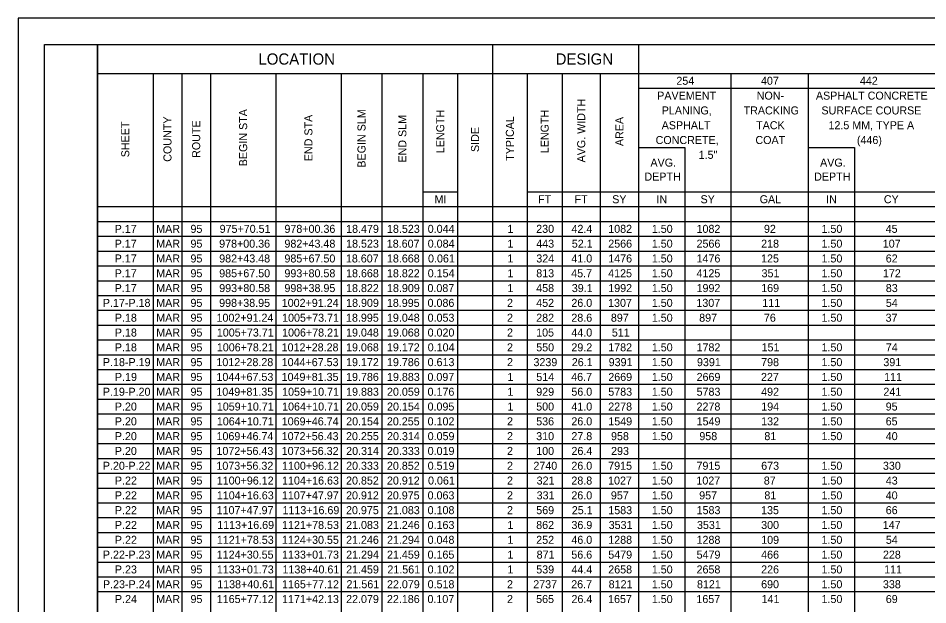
# Model space of a CAD drawing. Extents: x 0 to 34, y 0 to 22.
# Drawn here: x 0 to 17.22, y 10.91 to 22 of the extents above; entities that cross this region are included whole.
import ezdxf

# ---------------------------------------------------------------- set-up
doc = ezdxf.new("R2010")
doc.units = 0
for name, color, linetype in [('SH_Border', 7, 'Continuous'), ('SH_Cut_Line', 7, 'Continuous'), ('SH_Text', 7, 'Continuous')]:
    doc.layers.add(name, color=color, linetype=linetype)

msp = doc.modelspace()

# ---------------------------------------------------------------- linework, layer by layer
at = {"layer": 'SH_Border'}
for points in [[(0.5, 21.5), (1.5, 21.5), (1.5, 0.5), (0.5, 0.5)], [(1.5, 21.5), (33.5, 21.5), (33.5, 0.5), (1.5, 0.5)]]:
    msp.add_lwpolyline(points, close=True, dxfattribs=at)
at = {"layer": 'SH_Cut_Line'}
msp.add_lwpolyline([(0, 0), (34, 0), (34, 22), (0, 22)], close=True, dxfattribs=at)
at = {"layer": 'SH_Text'}
for p, q in [((1.5, 21.5), (32.011, 21.5)), ((1.5, 21.5), (1.5, 0.512)), ((8.979, 21.5), (8.979, 0.792)), ((11.747, 21.5), (11.747, 0.512)), ((1.5, 20.956), (32.011, 20.956)), ((2.554, 20.956), (2.554, 7.233)), ((3.098, 20.956), (3.098, 7.233)), ((3.642, 20.956), (3.642, 7.233)), ((4.877, 20.956), (4.877, 7.233)), ((6.113, 20.956), (6.113, 7.233)), ((6.887, 20.956), (6.887, 7.233)), ((7.661, 20.956), (7.661, 7.233)), ((8.32, 20.956), (8.32, 7.233)), ((9.638, 20.956), (9.638, 3.592)), ((10.297, 20.956), (10.297, 0.792)), ((11.022, 20.956), (11.022, 0.792)), ((13.493, 20.956), (13.493, 0.512)), ((14.96, 20.956), (14.96, 0.512)), ((11.747, 20.676), (27.48, 20.676)), ((11.747, 19.556), (12.62, 19.556)), ((12.62, 19.556), (12.62, 0.512)), ((14.96, 19.556), (15.833, 19.556)), ((15.833, 19.556), (15.833, 0.512)), ((7.661, 18.716), (8.32, 18.716)), ((9.638, 18.716), (27.48, 18.716)), ((1.5, 18.436), (32.011, 18.436)), ((1.5, 18.156), (32.011, 18.156)), ((1.5, 17.876), (32.011, 17.876)), ((1.5, 17.596), (32.011, 17.596)), ((1.5, 17.315), (32.011, 17.315)), ((1.5, 17.035), (32.011, 17.035)), ((1.5, 16.755), (32.011, 16.755)), ((1.5, 16.475), (32.011, 16.475)), ((1.5, 16.195), (32.011, 16.195)), ((1.5, 15.915), (32.011, 15.915)), ((1.5, 15.635), (32.011, 15.635)), ((1.5, 15.355), (32.011, 15.355)), ((1.5, 15.075), (32.011, 15.075)), ((1.5, 14.795), (32.011, 14.795)), ((1.5, 14.515), (32.011, 14.515)), ((1.5, 14.235), (32.011, 14.235)), ((1.5, 13.955), (32.011, 13.955)), ((1.5, 13.675), (32.011, 13.675)), ((1.5, 13.395), (32.011, 13.395)), ((1.5, 13.114), (32.011, 13.114)), ((1.5, 12.834), (32.011, 12.834)), ((1.5, 12.554), (32.011, 12.554)), ((1.5, 12.274), (32.011, 12.274)), ((1.5, 11.994), (32.011, 11.994)), ((1.5, 11.714), (32.011, 11.714)), ((1.5, 11.434), (32.011, 11.434)), ((1.5, 11.154), (32.011, 11.154))]:
    msp.add_line(p, q, dxfattribs=at)

# ---------------------------------------------------------------- texts
for s, height, p in [('LOCATION', 0.2122, (4.548, 21.122)), ('DESIGN', 0.2122, (10.176, 21.122)), ('254', 0.1516, (12.462, 20.741)), ('407', 0.1516, (14.064, 20.741)), ('442', 0.1516, (15.937, 20.741)), ('PAVEMENT', 0.1516, (12.099, 20.46)), ('NON-', 0.1516, (13.983, 20.46)), ('ASPHALT CONCRETE', 0.15157, (15.104, 20.46)), ('PLANING,', 0.1516, (12.185, 20.18)), ('TRACKING', 0.1516, (13.735, 20.18)), ('SURFACE COURSE', 0.15157, (15.209, 20.18)), ('ASPHALT', 0.1516, (12.184, 19.9)), ('TACK', 0.1516, (13.972, 19.9)), ('12.5 MM, TYPE A', 0.15157, (15.342, 19.9)), ('CONCRETE,', 0.1516, (12.069, 19.62)), ('COAT', 0.1516, (13.959, 19.62)), ('(446)', 0.1516, (15.88, 19.62)), ('1.5"', 0.1516, (12.884, 19.34)), ('AVG. ', 0.1516, (11.971, 19.193)), ('AVG. ', 0.1516, (15.183, 19.193)), ('DEPTH', 0.1516, (11.857, 18.928)), ('DEPTH', 0.1516, (15.07, 18.928)), ('MI', 0.1516, (7.883, 18.5)), ('FT', 0.1516, (9.842, 18.5)), ('FT', 0.1516, (10.534, 18.5)), ('SY', 0.1516, (11.247, 18.5)), ('IN', 0.1516, (12.085, 18.5)), ('SY', 0.1516, (12.92, 18.5)), ('GAL', 0.1516, (14.039, 18.5)), ('IN', 0.1516, (15.298, 18.5)), ('CY', 0.1516, (16.39, 18.5)), ('P.17', 0.1516, (1.827, 17.94)), ('MAR', 0.1516, (2.614, 17.94)), ('95', 0.1516, (3.262, 17.94)), ('975+70.51', 0.1516, (3.814, 17.94)), ('978+00.36', 0.1516, (5.041, 17.94)), ('18.479', 0.1516, (6.209, 17.94)), ('18.523', 0.1516, (6.983, 17.94)), ('0.044', 0.1516, (7.754, 17.94)), ('1', 0.152, (9.263, 17.94)), ('230', 0.1516, (9.808, 17.94)), ('42.4', 0.1516, (10.476, 17.94)), ('1082', 0.1516, (11.172, 17.94)), ('1.50', 0.1516, (11.997, 17.94)), ('1082', 0.1516, (12.844, 17.94)), ('92', 0.1516, (14.12, 17.94)), ('1.50', 0.1516, (15.21, 17.94)), ('45', 0.1516, (16.425, 17.94)), ('P.17', 0.1516, (1.827, 17.66)), ('MAR', 0.1516, (2.614, 17.66)), ('95', 0.1516, (3.262, 17.66)), ('978+00.36', 0.1516, (3.805, 17.66)), ('982+43.48', 0.1516, (5.041, 17.66)), ('18.523', 0.1516, (6.209, 17.66)), ('18.607', 0.1516, (6.979, 17.66)), ('0.084', 0.1516, (7.754, 17.66)), ('1', 0.152, (9.263, 17.66)), ('443', 0.1516, (9.809, 17.66)), ('52.1', 0.1516, (10.482, 17.66)), ('2566', 0.1516, (11.172, 17.66)), ('1.50', 0.1516, (11.997, 17.66)), ('2566', 0.1516, (12.844, 17.66)), ('218', 0.1516, (14.067, 17.66)), ('1.50', 0.1516, (15.21, 17.66)), ('107', 0.1516, (16.37, 17.66)), ('P.17', 0.1516, (1.827, 17.38)), ('MAR', 0.1516, (2.614, 17.38)), ('95', 0.1516, (3.262, 17.38)), ('982+43.48', 0.1516, (3.806, 17.38)), ('985+67.50', 0.1516, (5.041, 17.38)), ('18.607', 0.1516, (6.205, 17.38)), ('18.668', 0.1516, (6.982, 17.38)), ('0.061', 0.1516, (7.76, 17.38)), ('1', 0.152, (9.263, 17.38)), ('324', 0.1516, (9.81, 17.38)), ('41.0', 0.1516, (10.474, 17.38)), ('1476', 0.1516, (11.172, 17.38)), ('1.50', 0.1516, (11.997, 17.38)), ('1476', 0.1516, (12.844, 17.38)), ('125', 0.1516, (14.066, 17.38)), ('1.50', 0.1516, (15.21, 17.38)), ('62', 0.1516, (16.426, 17.38)), ('P.17', 0.1516, (1.827, 17.1)), ('MAR', 0.1516, (2.614, 17.1)), ('95', 0.1516, (3.262, 17.1)), ('985+67.50', 0.1516, (3.806, 17.1)), ('993+80.58', 0.1516, (5.041, 17.1)), ('18.668', 0.1516, (6.208, 17.1)), ('18.822', 0.1516, (6.982, 17.1)), ('0.154', 0.1516, (7.754, 17.1)), ('1', 0.152, (9.263, 17.1)), ('813', 0.1516, (9.809, 17.1)), ('45.7', 0.1516, (10.471, 17.1)), ('4125', 0.1516, (11.171, 17.1)), ('1.50', 0.1516, (11.997, 17.1)), ('4125', 0.1516, (12.843, 17.1)), ('351', 0.1516, (14.075, 17.1)), ('1.50', 0.1516, (15.21, 17.1)), ('172', 0.1516, (16.373, 17.1)), ('P.17', 0.1516, (1.827, 16.82)), ('MAR', 0.1516, (2.614, 16.82)), ('95', 0.1516, (3.262, 16.82)), ('993+80.58', 0.1516, (3.806, 16.82)), ('998+38.95', 0.1516, (5.041, 16.82)), ('18.822', 0.1516, (6.208, 16.82)), ('18.909', 0.1516, (6.983, 16.82)), ('0.087', 0.1516, (7.749, 16.82)), ('1', 0.152, (9.263, 16.82)), ('458', 0.1516, (9.808, 16.82)), ('39.1', 0.1516, (10.482, 16.82)), ('1992', 0.1516, (11.172, 16.82)), ('1.50', 0.1516, (11.997, 16.82)), ('1992', 0.1516, (12.844, 16.82)), ('169', 0.1516, (14.068, 16.82)), ('1.50', 0.1516, (15.21, 16.82)), ('83', 0.1516, (16.427, 16.82)), ('P.17-P.18', 0.1516, (1.603, 16.54)), ('MAR', 0.1516, (2.614, 16.54)), ('95', 0.1516, (3.262, 16.54)), ('998+38.95', 0.1516, (3.805, 16.54)), ('1002+91.24', 0.1516, (4.99, 16.54)), ('18.909', 0.1516, (6.209, 16.54)), ('18.995', 0.1516, (6.981, 16.54)), ('0.086', 0.1516, (7.751, 16.54)), ('2', 0.152, (9.255, 16.54)), ('452', 0.1516, (9.808, 16.54)), ('26.0', 0.1516, (10.474, 16.54)), ('1307', 0.1516, (11.169, 16.54)), ('1.50', 0.1516, (11.997, 16.54)), ('1307', 0.1516, (12.841, 16.54)), ('111', 0.1516, (14.089, 16.54)), ('1.50', 0.1516, (15.21, 16.54)), ('54', 0.1516, (16.428, 16.54)), ('P.18', 0.1516, (1.83, 16.259)), ('MAR', 0.1516, (2.614, 16.259)), ('95', 0.1516, (3.262, 16.259)), ('1002+91.24', 0.1516, (3.755, 16.259)), ('1005+73.71', 0.1516, (4.997, 16.259)), ('18.995', 0.1516, (6.207, 16.259)), ('19.048', 0.1516, (6.982, 16.259)), ('0.053', 0.1516, (7.752, 16.259)), ('2', 0.152, (9.255, 16.259)), ('282', 0.1516, (9.808, 16.259)), ('28.6', 0.1516, (10.473, 16.259)), ('897', 0.1516, (11.222, 16.259)), ('1.50', 0.1516, (11.997, 16.259)), ('897', 0.1516, (12.894, 16.259)), ('76', 0.1516, (14.119, 16.259)), ('1.50', 0.1516, (15.21, 16.259)), ('37', 0.1516, (16.423, 16.259)), ('P.18', 0.1516, (1.83, 15.979)), ('MAR', 0.1516, (2.614, 15.979)), ('95', 0.1516, (3.262, 15.979)), ('1005+73.71', 0.1516, (3.761, 15.979)), ('1006+78.21', 0.1516, (4.997, 15.979)), ('19.048', 0.1516, (6.208, 15.979)), ('19.068', 0.1516, (6.982, 15.979)), ('0.020', 0.1516, (7.752, 15.979)), ('2', 0.152, (9.255, 15.979)), ('105', 0.1516, (9.807, 15.979)), ('44.0', 0.1516, (10.474, 15.979)), ('511', 0.1516, (11.24, 15.979)), ('P.18', 0.1516, (1.83, 15.699)), ('MAR', 0.1516, (2.614, 15.699)), ('95', 0.1516, (3.262, 15.699)), ('1006+78.21', 0.1516, (3.761, 15.699)), ('1012+28.28', 0.1516, (4.988, 15.699)), ('19.068', 0.1516, (6.208, 15.699)), ('19.172', 0.1516, (6.982, 15.699)), ('0.104', 0.1516, (7.754, 15.699)), ('2', 0.152, (9.255, 15.699)), ('550', 0.1516, (9.808, 15.699)), ('29.2', 0.1516, (10.474, 15.699)), ('1782', 0.1516, (11.172, 15.699)), ('1.50', 0.1516, (11.997, 15.699)), ('1782', 0.1516, (12.844, 15.699)), ('151', 0.1516, (14.075, 15.699)), ('1.50', 0.1516, (15.21, 15.699)), ('74', 0.1516, (16.428, 15.699)), ('P.18-P.19', 0.1516, (1.604, 15.419)), ('MAR', 0.1516, (2.614, 15.419)), ('95', 0.1516, (3.262, 15.419)), ('1012+28.28', 0.1516, (3.753, 15.419)), ('1044+67.53', 0.1516, (4.989, 15.419)), ('19.172', 0.1516, (6.208, 15.419)), ('19.786', 0.1516, (6.982, 15.419)), ('0.613', 0.1516, (7.752, 15.419)), ('2', 0.152, (9.255, 15.419)), ('3239', 0.1516, (9.756, 15.419)), ('26.1', 0.1516, (10.482, 15.419)), ('9391', 0.1516, (11.18, 15.419)), ('1.50', 0.1516, (11.997, 15.419)), ('9391', 0.1516, (12.852, 15.419)), ('798', 0.1516, (14.067, 15.419)), ('1.50', 0.1516, (15.21, 15.419)), ('391', 0.1516, (16.381, 15.419)), ('P.19', 0.1516, (1.832, 15.139)), ('MAR', 0.1516, (2.614, 15.139)), ('95', 0.1516, (3.262, 15.139)), ('1044+67.53', 0.1516, (3.754, 15.139)), ('1049+81.35', 0.1516, (4.988, 15.139)), ('19.786', 0.1516, (6.208, 15.139)), ('19.883', 0.1516, (6.983, 15.139)), ('0.097', 0.1516, (7.749, 15.139)), ('1', 0.152, (9.263, 15.139)), ('514', 0.1516, (9.81, 15.139)), ('46.7', 0.1516, (10.471, 15.139)), ('2669', 0.1516, (11.173, 15.139)), ('1.50', 0.1516, (11.997, 15.139)), ('2669', 0.1516, (12.845, 15.139)), ('227', 0.1516, (14.064, 15.139)), ('1.50', 0.1516, (15.21, 15.139)), ('111', 0.1516, (16.396, 15.139)), ('P.19-P.20', 0.1516, (1.603, 14.859)), ('MAR', 0.1516, (2.614, 14.859)), ('95', 0.1516, (3.262, 14.859)), ('1049+81.35', 0.1516, (3.752, 14.859)), ('1059+10.71', 0.1516, (4.997, 14.859)), ('19.883', 0.1516, (6.209, 14.859)), ('20.059', 0.1516, (6.983, 14.859)), ('0.176', 0.1516, (7.751, 14.859)), ('1', 0.152, (9.263, 14.859)), ('929', 0.1516, (9.809, 14.859)), ('56.0', 0.1516, (10.474, 14.859)), ('5783', 0.1516, (11.173, 14.859)), ('1.50', 0.1516, (11.997, 14.859)), ('5783', 0.1516, (12.845, 14.859)), ('492', 0.1516, (14.067, 14.859)), ('1.50', 0.1516, (15.21, 14.859)), ('241', 0.1516, (16.381, 14.859)), ('P.20', 0.1516, (1.83, 14.579)), ('MAR', 0.1516, (2.614, 14.579)), ('95', 0.1516, (3.262, 14.579)), ('1059+10.71', 0.1516, (3.761, 14.579)), ('1064+10.71', 0.1516, (4.997, 14.579)), ('20.059', 0.1516, (6.209, 14.579)), ('20.154', 0.1516, (6.984, 14.579)), ('0.095', 0.1516, (7.751, 14.579)), ('1', 0.152, (9.263, 14.579)), ('500', 0.1516, (9.808, 14.579)), ('41.0', 0.1516, (10.474, 14.579)), ('2278', 0.1516, (11.172, 14.579)), ('1.50', 0.1516, (11.997, 14.579)), ('2278', 0.1516, (12.844, 14.579)), ('194', 0.1516, (14.069, 14.579)), ('1.50', 0.1516, (15.21, 14.579)), ('95', 0.1516, (16.425, 14.579)), ('P.20', 0.1516, (1.83, 14.299)), ('MAR', 0.1516, (2.614, 14.299)), ('95', 0.1516, (3.262, 14.299)), ('1064+10.71', 0.1516, (3.761, 14.299)), ('1069+46.74', 0.1516, (4.99, 14.299)), ('20.154', 0.1516, (6.21, 14.299)), ('20.255', 0.1516, (6.981, 14.299)), ('0.102', 0.1516, (7.752, 14.299)), ('2', 0.152, (9.255, 14.299)), ('536', 0.1516, (9.808, 14.299)), ('26.0', 0.1516, (10.474, 14.299)), ('1549', 0.1516, (11.173, 14.299)), ('1.50', 0.1516, (11.997, 14.299)), ('1549', 0.1516, (12.845, 14.299)), ('132', 0.1516, (14.067, 14.299)), ('1.50', 0.1516, (15.21, 14.299)), ('65', 0.1516, (16.425, 14.299)), ('P.20', 0.1516, (1.83, 14.019)), ('MAR', 0.1516, (2.614, 14.019)), ('95', 0.1516, (3.262, 14.019)), ('1069+46.74', 0.1516, (3.755, 14.019)), ('1072+56.43', 0.1516, (4.989, 14.019)), ('20.255', 0.1516, (6.207, 14.019)), ('20.314', 0.1516, (6.984, 14.019)), ('0.059', 0.1516, (7.753, 14.019)), ('2', 0.152, (9.255, 14.019)), ('310', 0.1516, (9.808, 14.019)), ('27.8', 0.1516, (10.474, 14.019)), ('958', 0.1516, (11.225, 14.019)), ('1.50', 0.1516, (11.997, 14.019)), ('958', 0.1516, (12.897, 14.019)), ('81', 0.1516, (14.128, 14.019)), ('1.50', 0.1516, (15.21, 14.019)), ('40', 0.1516, (16.426, 14.019)), ('P.20', 0.1516, (1.83, 13.739)), ('MAR', 0.1516, (2.614, 13.739)), ('95', 0.1516, (3.262, 13.739)), ('1072+56.43', 0.1516, (3.754, 13.739)), ('1073+56.32', 0.1516, (4.989, 13.739)), ('20.314', 0.1516, (6.21, 13.739)), ('20.333', 0.1516, (6.983, 13.739)), ('0.019', 0.1516, (7.753, 13.739)), ('2', 0.152, (9.255, 13.739)), ('100', 0.1516, (9.808, 13.739)), ('26.4', 0.1516, (10.476, 13.739)), ('293', 0.1516, (11.226, 13.739)), ('P.20-P.22', 0.1516, (1.603, 13.459)), ('MAR', 0.1516, (2.614, 13.459)), ('95', 0.1516, (3.262, 13.459)), ('1073+56.32', 0.1516, (3.753, 13.459)), ('1100+96.12', 0.1516, (4.996, 13.459)), ('20.333', 0.1516, (6.209, 13.459)), ('20.852', 0.1516, (6.982, 13.459)), ('0.519', 0.1516, (7.753, 13.459)), ('2', 0.152, (9.255, 13.459)), ('2740', 0.1516, (9.755, 13.459)), ('26.0', 0.1516, (10.474, 13.459)), ('7915', 0.1516, (11.171, 13.459)), ('1.50', 0.1516, (11.997, 13.459)), ('7915', 0.1516, (12.843, 13.459)), ('673', 0.1516, (14.068, 13.459)), ('1.50', 0.1516, (15.21, 13.459)), ('330', 0.1516, (16.373, 13.459)), ('P.22', 0.1516, (1.831, 13.179)), ('MAR', 0.1516, (2.614, 13.179)), ('95', 0.1516, (3.262, 13.179)), ('1100+96.12', 0.1516, (3.76, 13.179)), ('1104+16.63', 0.1516, (4.996, 13.179)), ('20.852', 0.1516, (6.208, 13.179)), ('20.912', 0.1516, (6.982, 13.179)), ('0.061', 0.1516, (7.76, 13.179)), ('2', 0.152, (9.255, 13.179)), ('321', 0.1516, (9.816, 13.179)), ('28.8', 0.1516, (10.474, 13.179)), ('1027', 0.1516, (11.169, 13.179)), ('1.50', 0.1516, (11.997, 13.179)), ('1027', 0.1516, (12.841, 13.179)), ('87', 0.1516, (14.117, 13.179)), ('1.50', 0.1516, (15.21, 13.179)), ('43', 0.1516, (16.427, 13.179)), ('P.22', 0.1516, (1.831, 12.899)), ('MAR', 0.1516, (2.614, 12.899)), ('95', 0.1516, (3.262, 12.899)), ('1104+16.63', 0.1516, (3.761, 12.899)), ('1107+47.97', 0.1516, (4.993, 12.899)), ('20.912', 0.1516, (6.208, 12.899)), ('20.975', 0.1516, (6.981, 12.899)), ('0.063', 0.1516, (7.752, 12.899)), ('2', 0.152, (9.255, 12.899)), ('331', 0.1516, (9.816, 12.899)), ('26.0', 0.1516, (10.474, 12.899)), ('957', 0.1516, (11.222, 12.899)), ('1.50', 0.1516, (11.997, 12.899)), ('957', 0.1516, (12.894, 12.899)), ('81', 0.1516, (14.128, 12.899)), ('1.50', 0.1516, (15.21, 12.899)), ('40', 0.1516, (16.426, 12.899)), ('P.22', 0.1516, (1.831, 12.619)), ('MAR', 0.1516, (2.614, 12.619)), ('95', 0.1516, (3.262, 12.619)), ('1107+47.97', 0.1516, (3.757, 12.619)), ('1113+16.69', 0.1516, (5.004, 12.619)), ('20.975', 0.1516, (6.207, 12.619)), ('21.083', 0.1516, (6.983, 12.619)), ('0.108', 0.1516, (7.752, 12.619)), ('2', 0.152, (9.255, 12.619)), ('569', 0.1516, (9.809, 12.619)), ('25.1', 0.1516, (10.482, 12.619)), ('1583', 0.1516, (11.173, 12.619)), ('1.50', 0.1516, (11.997, 12.619)), ('1583', 0.1516, (12.845, 12.619)), ('135', 0.1516, (14.066, 12.619)), ('1.50', 0.1516, (15.21, 12.619)), ('66', 0.1516, (16.426, 12.619)), ('P.22', 0.1516, (1.831, 12.339)), ('MAR', 0.1516, (2.614, 12.339)), ('95', 0.1516, (3.262, 12.339)), ('1113+16.69', 0.1516, (3.768, 12.339)), ('1121+78.53', 0.1516, (4.996, 12.339)), ('21.083', 0.1516, (6.209, 12.339)), ('21.246', 0.1516, (6.982, 12.339)), ('0.163', 0.1516, (7.752, 12.339)), ('1', 0.152, (9.263, 12.339)), ('862', 0.1516, (9.808, 12.339)), ('36.9', 0.1516, (10.475, 12.339)), ('3531', 0.1516, (11.18, 12.339)), ('1.50', 0.1516, (11.997, 12.339)), ('3531', 0.1516, (12.852, 12.339)), ('300', 0.1516, (14.067, 12.339)), ('1.50', 0.1516, (15.21, 12.339)), ('147', 0.1516, (16.37, 12.339)), ('P.22', 0.1516, (1.831, 12.058)), ('MAR', 0.1516, (2.614, 12.058)), ('95', 0.1516, (3.262, 12.058)), ('1121+78.53', 0.1516, (3.761, 12.058)), ('1124+30.55', 0.1516, (4.995, 12.058)), ('21.246', 0.1516, (6.208, 12.058)), ('21.294', 0.1516, (6.984, 12.058)), ('0.048', 0.1516, (7.752, 12.058)), ('1', 0.152, (9.263, 12.058)), ('252', 0.1516, (9.808, 12.058)), ('46.0', 0.1516, (10.474, 12.058)), ('1288', 0.1516, (11.172, 12.058)), ('1.50', 0.1516, (11.997, 12.058)), ('1288', 0.1516, (12.844, 12.058)), ('109', 0.1516, (14.068, 12.058)), ('1.50', 0.1516, (15.21, 12.058)), ('54', 0.1516, (16.428, 12.058)), ('P.22-P.23', 0.1516, (1.603, 11.778)), ('MAR', 0.1516, (2.614, 11.778)), ('95', 0.1516, (3.262, 11.778)), ('1124+30.55', 0.1516, (3.759, 11.778)), ('1133+01.73', 0.1516, (4.996, 11.778)), ('21.294', 0.1516, (6.21, 11.778)), ('21.459', 0.1516, (6.983, 11.778)), ('0.165', 0.1516, (7.751, 11.778)), ('1', 0.152, (9.263, 11.778)), ('871', 0.1516, (9.816, 11.778)), ('56.6', 0.1516, (10.473, 11.778)), ('5479', 0.1516, (11.173, 11.778)), ('1.50', 0.1516, (11.997, 11.778)), ('5479', 0.1516, (12.845, 11.778)), ('466', 0.1516, (14.067, 11.778)), ('1.50', 0.1516, (15.21, 11.778)), ('228', 0.1516, (16.373, 11.778)), ('P.23', 0.1516, (1.831, 11.498)), ('MAR', 0.1516, (2.614, 11.498)), ('95', 0.1516, (3.262, 11.498)), ('1133+01.73', 0.1516, (3.761, 11.498)), ('1138+40.61', 0.1516, (5.004, 11.498)), ('21.459', 0.1516, (6.209, 11.498)), ('21.561', 0.1516, (6.99, 11.498)), ('0.102', 0.1516, (7.752, 11.498)), ('1', 0.152, (9.263, 11.498)), ('539', 0.1516, (9.809, 11.498)), ('44.4', 0.1516, (10.476, 11.498)), ('2658', 0.1516, (11.172, 11.498)), ('1.50', 0.1516, (11.997, 11.498)), ('2658', 0.1516, (12.844, 11.498)), ('226', 0.1516, (14.067, 11.498)), ('1.50', 0.1516, (15.21, 11.498)), ('111', 0.1516, (16.396, 11.498)), ('P.23-P.24', 0.1516, (1.605, 11.218)), ('MAR', 0.1516, (2.614, 11.218)), ('95', 0.1516, (3.262, 11.218)), ('1138+40.61', 0.1516, (3.768, 11.218)), ('1165+77.12', 0.1516, (4.996, 11.218)), ('21.561', 0.1516, (6.216, 11.218)), ('22.079', 0.1516, (6.983, 11.218)), ('0.518', 0.1516, (7.752, 11.218)), ('2', 0.152, (9.255, 11.218)), ('2737', 0.1516, (9.752, 11.218)), ('26.7', 0.1516, (10.471, 11.218)), ('8121', 0.1516, (11.18, 11.218)), ('1.50', 0.1516, (11.997, 11.218)), ('8121', 0.1516, (12.852, 11.218)), ('690', 0.1516, (14.067, 11.218)), ('1.50', 0.1516, (15.21, 11.218)), ('338', 0.1516, (16.373, 11.218)), ('P.24', 0.1516, (1.832, 10.938)), ('MAR', 0.1516, (2.614, 10.938)), ('95', 0.1516, (3.262, 10.938)), ('1165+77.12', 0.1516, (3.76, 10.938)), ('1171+42.13', 0.1516, (4.996, 10.938)), ('22.079', 0.1516, (6.209, 10.938)), ('22.186', 0.1516, (6.982, 10.938)), ('0.107', 0.1516, (7.749, 10.938)), ('2', 0.152, (9.255, 10.938)), ('565', 0.1516, (9.807, 10.938)), ('26.4', 0.1516, (10.476, 10.938)), ('1657', 0.1516, (11.169, 10.938)), ('1.50', 0.1516, (11.997, 10.938)), ('1657', 0.1516, (12.841, 10.938)), ('141', 0.1516, (14.075, 10.938)), ('1.50', 0.1516, (15.21, 10.938)), ('69', 0.1516, (16.427, 10.938))]:
    msp.add_text(s, height=height, dxfattribs=at).set_placement(p)
for s, p in [('AVG. WIDTH', (10.736, 19.272)), ('BEGIN STA', (4.335, 19.199)), ('END STA', (5.571, 19.295)), ('BEGIN SLM', (6.576, 19.173)), ('END SLM', (7.35, 19.269)), ('LENGTH', (8.067, 19.446)), ('LENGTH', (10.044, 19.446)), ('SHEET', (2.103, 19.369)), ('COUNTY', (2.902, 19.284)), ('ROUTE', (3.446, 19.358)), ('TYPICAL', (9.385, 19.302)), ('AREA', (11.46, 19.581)), ('SIDE', (8.726, 19.469))]:
    msp.add_text(s, height=0.1516, rotation=90, dxfattribs=at).set_placement(p)

doc.saveas('drawing.dxf')
